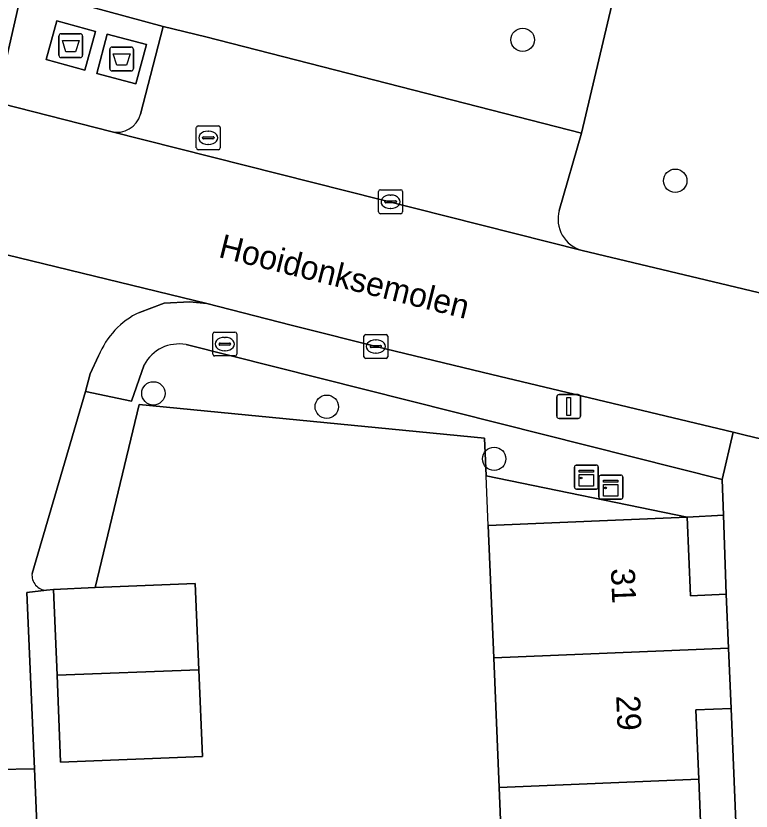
# Model space of a CAD drawing. Extents: x 161241 to 161758, y 384138 to 384885.
# Drawn here: x 161336.04 to 161366.81, y 384281.92 to 384315.21 of the extents above; entities that cross this region are included whole.
import ezdxf

# ---------------------------------------------------------------- set-up
doc = ezdxf.new("R2010")
doc.units = 0
for name, color, linetype in [('IMGEO_Afval_apart_plaats', 7, 'Continuous'), ('IMGEO_Boom', 7, 'Continuous'), ('IMGEO_Erf', 7, 'Continuous'), ('IMGEO_Groenvoorziening', 7, 'Continuous'), ('IMGEO_Hek', 7, 'Continuous'), ('IMGEO_Kast', 7, 'Continuous'), ('IMGEO_Kolk', 7, 'Continuous'), ('IMGEO_Lichtmast', 7, 'Continuous'), ('IMGEO_Openbare_ruimte_label', 7, 'Continuous'), ('IMGEO_Pand', 7, 'Continuous'), ('IMGEO_Pand_nummerreeks', 7, 'Continuous'), ('IMGEO_Parkeervlak_open', 7, 'Continuous'), ('IMGEO_Rijbaan_lokaal_open', 7, 'Continuous'), ('IMGEO_Rioolput', 7, 'Continuous'), ('IMGEO_Voetpad_gesloten', 7, 'Continuous'), ('IMGEO_Voetpad_open', 7, 'Continuous')]:
    doc.layers.add(name, color=color, linetype=linetype)

msp = doc.modelspace()

# ---------------------------------------------------------------- linework, layer by layer
at = {"layer": 'IMGEO_Afval_apart_plaats'}
for p, q in [((161337.939, 384314.467), (161338.729, 384314.467)), ((161338.729, 384314.467), (161337.939, 384314.467)), ((161337.839, 384313.567), (161337.839, 384314.367)), ((161337.839, 384314.367), (161337.839, 384313.567)), ((161338.829, 384314.367), (161338.829, 384313.567)), ((161338.829, 384313.567), (161338.829, 384314.367)), ((161339.968, 384313.008), (161339.968, 384313.808)), ((161339.968, 384313.808), (161339.968, 384313.008)), ((161340.068, 384313.908), (161340.858, 384313.908)), ((161340.858, 384313.908), (161340.068, 384313.908)), ((161340.958, 384313.808), (161340.958, 384313.008)), ((161340.958, 384313.008), (161340.958, 384313.808)), ((161338.729, 384313.467), (161337.939, 384313.467)), ((161337.939, 384313.467), (161338.729, 384313.467)), ((161340.858, 384312.908), (161340.068, 384312.908)), ((161340.068, 384312.908), (161340.858, 384312.908))]:
    msp.add_line(p, q, dxfattribs=at)
for points in [[(161337.982, 384314.181), (161338.686, 384314.181), (161338.537, 384313.711), (161338.131, 384313.711), (161337.982, 384314.181)], [(161340.111, 384313.622), (161340.815, 384313.622), (161340.666, 384313.152), (161340.26, 384313.152), (161340.111, 384313.622)]]:
    msp.add_lwpolyline(points, dxfattribs=at)
for centre, start, end in [((161337.939, 384314.367), 90, 180), ((161337.939, 384314.367), 90, 180), ((161338.729, 384314.367), 0, 90), ((161338.729, 384314.367), 360, 90), ((161340.068, 384313.808), 90, 180), ((161340.068, 384313.808), 90, 180), ((161340.858, 384313.808), 0, 90), ((161340.858, 384313.808), 360, 90), ((161337.939, 384313.567), 180, 270), ((161337.939, 384313.567), 180, 270), ((161338.729, 384313.567), 270, 0), ((161338.729, 384313.567), 270, 0), ((161340.068, 384313.008), 180, 270), ((161340.068, 384313.008), 180, 270), ((161340.858, 384313.008), 270, 0), ((161340.858, 384313.008), 270, 0)]:
    msp.add_arc(centre, 0.1, start, end, dxfattribs=at)
at = {"layer": 'IMGEO_Boom'}
for centre in [(161357.246, 384314.213), (161363.632, 384308.312), (161341.792, 384299.412), (161349.048, 384298.852), (161356.052, 384296.67)]:
    msp.add_circle(centre, 0.489, dxfattribs=at)
at = {"layer": 'IMGEO_Erf'}
msp.add_lwpolyline([(161356.488, 384277.486), (161356.262, 384282.909), (161356.035, 384288.333), (161355.803, 384293.876), (161364.129, 384294.223), (161355.716, 384295.962), (161355.65, 384297.533), (161341.191, 384298.94), (161339.356, 384291.278), (161343.541, 384291.452), (161343.692, 384287.843), (161343.843, 384284.212), (161337.91, 384283.965), (161337.758, 384287.607), (161337.608, 384291.205), (161337.32, 384291.17), (161336.501, 384291.074), (161336.819, 384283.698), (161338.239, 384250)], dxfattribs=at)
for points in [[(161364.129, 384294.223), (161364.266, 384290.938), (161365.768, 384291), (161365.649, 384294.31)], [(161365.967, 384286.221), (161364.492, 384286.16), (161364.613, 384283.257), (161364.747, 384280.045), (161366.223, 384280.106)]]:
    msp.add_lwpolyline(points, close=True, dxfattribs=at)
at = {"layer": 'IMGEO_Groenvoorziening'}
for points in [[(161359.736, 384305.395), (161365.529, 384304.017), (161372.24, 384302.407), (161373.142, 384302.222), (161374.439, 384312.732), (161374.623, 384314.221), (161375.299, 384319.702), (161358.812, 384321.618), (161359.31, 384326.016), (161359.827, 384330.585), (161358.63, 384330.717), (161361.21, 384352.499), (161349.287, 384353.883), (161348.839, 384353.935), (161345.806, 384318.051), (161360.974, 384315.683), (161359.706, 384310.307), (161358.781, 384307.069)], [(161328.866, 384324.519), (161328.421, 384321.506), (161295.885, 384325.211), (161295.467, 384325.102), (161295.374, 384323.02), (161335.524, 384312.89), (161338.358, 384325.391), (161331.006, 384326.163)], [(161337.32, 384291.17), (161337.608, 384291.205), (161339.356, 384291.278), (161341.191, 384298.94), (161355.65, 384297.533), (161355.716, 384295.962), (161364.129, 384294.223), (161365.649, 384294.31), (161365.595, 384295.806), (161343.158, 384301.452)], [(161341.404, 384300.609), (161340.871, 384299.087), (161338.948, 384299.496), (161336.713, 384291.871)]]:
    msp.add_lwpolyline(points, dxfattribs=at)
msp.add_lwpolyline([(161337.862, 384317.338), (161337.568, 384316.046), (161342.197, 384314.772), (161343.987, 384314.34), (161359.706, 384310.307), (161360.974, 384315.683), (161345.806, 384318.051), (161338.281, 384319.226)], close=True, dxfattribs=at)
for centre, radius, start, end in [((161360.076, 384306.698), 1.347, 164.0327, 255.3759), ((161342.862, 384299.822), 1.657, 79.7112, 151.6282), ((161337.341, 384291.801), 0.631, 173.6444, 268.1346)]:
    msp.add_arc(centre, radius, start, end, dxfattribs=at)
at = {"layer": 'IMGEO_Hek'}
msp.add_lwpolyline([(161355.803, 384293.876), (161355.716, 384295.962)], dxfattribs=at)
at = {"layer": 'IMGEO_Kast'}
for p, q in [((161359.411, 384295.48), (161359.411, 384296.321)), ((161359.411, 384296.321), (161359.411, 384295.48)), ((161359.486, 384296.405), (161360.327, 384296.405)), ((161360.327, 384296.405), (161359.486, 384296.405)), ((161360.411, 384296.33), (161360.411, 384295.489)), ((161360.411, 384295.489), (161360.411, 384296.33)), ((161360.439, 384295.062), (161360.439, 384295.903)), ((161360.439, 384295.903), (161360.439, 384295.062)), ((161360.514, 384295.987), (161361.355, 384295.987)), ((161361.355, 384295.987), (161360.514, 384295.987)), ((161361.439, 384295.912), (161361.439, 384295.071)), ((161361.439, 384295.071), (161361.439, 384295.912)), ((161360.336, 384295.405), (161359.495, 384295.405)), ((161359.495, 384295.405), (161360.336, 384295.405)), ((161361.364, 384294.987), (161360.523, 384294.987)), ((161360.523, 384294.987), (161361.364, 384294.987))]:
    msp.add_line(p, q, dxfattribs=at)
for points in [[(161359.606, 384296.195), (161360.206, 384296.195), (161360.206, 384296.11), (161359.606, 384296.11), (161359.606, 384296.195)], [(161359.606, 384296.02), (161360.206, 384296.02), (161360.206, 384295.531), (161359.606, 384295.531), (161359.606, 384296.02)], [(161360.634, 384295.777), (161361.234, 384295.777), (161361.234, 384295.692), (161360.634, 384295.692), (161360.634, 384295.777)], [(161360.634, 384295.602), (161361.234, 384295.602), (161361.234, 384295.113), (161360.634, 384295.113), (161360.634, 384295.602)]]:
    msp.add_lwpolyline(points, dxfattribs=at)
for centre in [(161359.69, 384295.869), (161360.718, 384295.451)]:
    msp.add_circle(centre, 0.0377, dxfattribs=at)
for centre, start, end in [((161359.489, 384296.327), 92.4484, 184.2845), ((161359.489, 384296.327), 92.4484, 184.2845), ((161360.333, 384296.327), 2.4484, 94.2845), ((161360.333, 384296.327), 2.4484, 94.2845), ((161360.517, 384295.909), 92.4484, 184.2845), ((161360.517, 384295.909), 92.4484, 184.2845), ((161361.361, 384295.909), 2.4484, 94.2845), ((161361.361, 384295.909), 2.4484, 94.2845), ((161359.489, 384295.483), 182.4484, 274.2845), ((161359.489, 384295.483), 182.4484, 274.2845), ((161360.333, 384295.483), 272.4484, 4.2845), ((161360.333, 384295.483), 272.4484, 4.2845), ((161360.517, 384295.065), 182.4484, 274.2845), ((161360.517, 384295.065), 182.4484, 274.2845), ((161361.361, 384295.065), 272.4484, 4.2845), ((161361.361, 384295.065), 272.4484, 4.2845)]:
    msp.add_arc(centre, 0.0779, start, end, dxfattribs=at)
at = {"layer": 'IMGEO_Kolk'}
for p, q in [((161351.219, 384307.008), (161351.219, 384307.86)), ((161351.294, 384307.934), (161352.146, 384307.934)), ((161352.22, 384307.86), (161352.22, 384307.008)), ((161351.478, 384307.428), (161351.478, 384307.44)), ((161351.521, 384307.477), (161351.919, 384307.477)), ((161351.707, 384307.714), (161351.732, 384307.714)), ((161351.962, 384307.44), (161351.962, 384307.428)), ((161351.916, 384307.391), (161351.518, 384307.391)), ((161351.73, 384307.154), (161351.705, 384307.154)), ((161352.146, 384306.934), (161351.294, 384306.934)), ((161350.602, 384300.947), (161350.602, 384301.799)), ((161350.677, 384301.873), (161351.529, 384301.873)), ((161351.603, 384301.799), (161351.603, 384300.947)), ((161350.904, 384301.416), (161351.302, 384301.416)), ((161351.09, 384301.653), (161351.115, 384301.653)), ((161350.861, 384301.367), (161350.861, 384301.379)), ((161351.299, 384301.33), (161350.901, 384301.33)), ((161351.113, 384301.093), (161351.088, 384301.093)), ((161351.345, 384301.379), (161351.345, 384301.367)), ((161351.529, 384300.873), (161350.677, 384300.873))]:
    msp.add_line(p, q, dxfattribs=at)
for points in [[(161351.219, 384307.008), (161351.219, 384307.86)], [(161351.294, 384307.934), (161352.146, 384307.934)], [(161352.22, 384307.86), (161352.22, 384307.008)], [(161352.146, 384306.934), (161351.294, 384306.934)], [(161350.602, 384300.947), (161350.602, 384301.799)], [(161350.677, 384301.873), (161351.529, 384301.873)], [(161351.603, 384301.799), (161351.603, 384300.947)], [(161351.529, 384300.873), (161350.677, 384300.873)]]:
    msp.add_lwpolyline(points, dxfattribs=at)
for centre, radius, start, end in [((161351.296, 384307.858), 0.0765, 91.552, 178.448), ((161351.296, 384307.858), 0.0765, 91.552, 178.448), ((161352.144, 384307.858), 0.0765, 1.552, 88.448), ((161352.144, 384307.858), 0.0765, 1.552, 88.448), ((161351.518, 384307.437), 0.0403, 85.8775, 175.7526), ((161351.515, 384307.427), 0.0366, 178.938, 274.7102), ((161351.919, 384307.434), 0.043, 264.8664, 352.4533), ((161351.923, 384307.439), 0.0386, 1.7309, 96.639), ((161351.296, 384307.01), 0.0765, 181.552, 268.448), ((161351.296, 384307.01), 0.0765, 181.552, 268.448), ((161352.144, 384307.01), 0.0765, 271.552, 358.448), ((161352.144, 384307.01), 0.0765, 271.552, 358.448), ((161350.679, 384301.797), 0.0765, 91.552, 178.448), ((161350.679, 384301.797), 0.0765, 91.552, 178.448), ((161351.527, 384301.797), 0.0765, 1.552, 88.448), ((161351.527, 384301.797), 0.0765, 1.552, 88.448), ((161350.901, 384301.376), 0.0403, 85.8775, 175.7526), ((161351.306, 384301.378), 0.0386, 1.7309, 96.639), ((161350.898, 384301.366), 0.0366, 178.938, 274.7102), ((161351.302, 384301.373), 0.043, 264.8664, 352.4533), ((161350.679, 384300.949), 0.0765, 181.552, 268.448), ((161350.679, 384300.949), 0.0765, 181.552, 268.448), ((161351.527, 384300.949), 0.0765, 271.552, 358.448), ((161351.527, 384300.949), 0.0765, 271.552, 358.448)]:
    msp.add_arc(centre, radius, start, end, dxfattribs=at)
for centre, major_axis, ratio, start_param, end_param in [((161351.706, 384307.434), (-0.387, 0.002), 0.722429, 4.712389, 7.853982), ((161351.731, 384307.434), (-0.39, 0.002), 0.717154, 1.570796, 4.712389), ((161351.089, 384301.373), (-0.387, 0.002), 0.722429, 4.712389, 7.853982), ((161351.114, 384301.373), (-0.39, 0.002), 0.717154, 1.570796, 4.712389)]:
    msp.add_ellipse(centre, major_axis=major_axis, ratio=ratio, start_param=start_param, end_param=end_param, dxfattribs=at)
at = {"layer": 'IMGEO_Lichtmast'}
for p, q in [((161358.674, 384298.46), (161358.674, 384299.26)), ((161358.674, 384299.26), (161358.674, 384298.46)), ((161358.774, 384299.36), (161359.564, 384299.36)), ((161359.564, 384299.36), (161358.774, 384299.36)), ((161359.664, 384299.26), (161359.664, 384298.46)), ((161359.664, 384298.46), (161359.664, 384299.26)), ((161359.564, 384298.36), (161358.774, 384298.36)), ((161358.774, 384298.36), (161359.564, 384298.36))]:
    msp.add_line(p, q, dxfattribs=at)
msp.add_lwpolyline([(161359.094, 384299.235), (161359.244, 384299.235), (161359.244, 384298.485), (161359.094, 384298.485), (161359.094, 384299.235)], dxfattribs=at)
for centre, start, end in [((161358.774, 384299.26), 90, 180), ((161358.774, 384299.26), 90, 180), ((161359.564, 384299.26), 0, 90), ((161359.564, 384299.26), 360, 90), ((161358.774, 384298.46), 180, 270), ((161358.774, 384298.46), 180, 270), ((161359.564, 384298.46), 270, 0), ((161359.564, 384298.46), 270, 0)]:
    msp.add_arc(centre, 0.1, start, end, dxfattribs=at)
at = {"layer": 'IMGEO_Pand'}
for points in [[(161365.768, 384291), (161364.266, 384290.938), (161364.129, 384294.223), (161355.803, 384293.876), (161356.035, 384288.333), (161365.862, 384288.743)], [(161337.608, 384291.205), (161337.758, 384287.607), (161343.692, 384287.843), (161343.541, 384291.452), (161339.356, 384291.278)], [(161365.862, 384288.743), (161356.035, 384288.333), (161356.262, 384282.909), (161364.613, 384283.257), (161364.492, 384286.16), (161365.967, 384286.221)], [(161337.758, 384287.607), (161337.91, 384283.965), (161343.843, 384284.212), (161343.692, 384287.843)], [(161366.223, 384280.106), (161364.747, 384280.045), (161364.613, 384283.257), (161356.262, 384282.909), (161356.488, 384277.486), (161366.315, 384277.896)]]:
    msp.add_lwpolyline(points, close=True, dxfattribs=at)
at = {"layer": 'IMGEO_Parkeervlak_open'}
for points in [[(161358.781, 384307.069), (161359.706, 384310.307), (161343.987, 384314.34), (161342.197, 384314.772), (161341.253, 384311.101)], [(161340.013, 384310.37), (161359.736, 384305.395)]]:
    msp.add_lwpolyline(points, dxfattribs=at)
for centre, radius, start, end in [((161340.26, 384311.368), 1.028, 256.0742, 344.9659), ((161360.076, 384306.698), 1.347, 164.0327, 255.3759)]:
    msp.add_arc(centre, radius, start, end, dxfattribs=at)
at = {"layer": 'IMGEO_Rijbaan_lokaal_open'}
for points in [[(161314.233, 384310.619), (161318.239, 384309.618), (161324.227, 384308.123), (161331.236, 384306.334), (161332.498, 384305.981), (161344.034, 384303.169), (161347.56, 384302.264), (161351.506, 384301.273), (161355.95, 384300.205), (161366.059, 384297.781), (161366.499, 384297.676), (161371.443, 384296.485), (161372.24, 384302.407), (161365.529, 384304.017), (161359.736, 384305.395), (161340.013, 384310.37), (161334.145, 384311.868), (161312.768, 384317.162), (161299.409, 384320.514), (161296.499, 384321.254), (161295.059, 384315.515), (161302.851, 384313.529), (161304.825, 384312.536)], [(161341.207, 384302.802), (161342.239, 384303.19), (161343.315, 384303.25), (161344.034, 384303.169), (161332.498, 384305.981)], [(161334.475, 384301.885), (161334.078, 384300.633), (161331.745, 384292.799), (161333.39, 384292.341), (161333.505, 384290.009), (161333.601, 384287.108), (161333.712, 384285.206), (161333.749, 384283.665), (161335.259, 384283.661), (161336.819, 384283.698), (161336.501, 384291.074), (161337.32, 384291.17)], [(161338.948, 384299.496), (161339.149, 384300.233), (161339.5, 384300.988)], [(161336.713, 384291.871), (161338.948, 384299.496)]]:
    msp.add_lwpolyline(points, dxfattribs=at)
for centre, radius, start, end in [((161342.692, 384299.695), 3.444, 115.5396, 157.9416), ((161337.341, 384291.801), 0.631, 173.6444, 268.1346)]:
    msp.add_arc(centre, radius, start, end, dxfattribs=at)
at = {"layer": 'IMGEO_Rioolput'}
for p, q in [((161343.589, 384309.684), (161343.589, 384310.536)), ((161343.664, 384310.61), (161344.516, 384310.61)), ((161344.59, 384310.536), (161344.59, 384309.684)), ((161343.848, 384310.104), (161343.848, 384310.116)), ((161343.891, 384310.153), (161344.289, 384310.153)), ((161344.077, 384310.39), (161344.102, 384310.39)), ((161344.332, 384310.116), (161344.332, 384310.104)), ((161344.286, 384310.067), (161343.888, 384310.067)), ((161344.1, 384309.83), (161344.075, 384309.83)), ((161344.516, 384309.61), (161343.664, 384309.61)), ((161344.28, 384301.05), (161344.28, 384301.902)), ((161344.355, 384301.976), (161345.207, 384301.976)), ((161344.768, 384301.756), (161344.793, 384301.756)), ((161345.281, 384301.902), (161345.281, 384301.05)), ((161344.539, 384301.47), (161344.539, 384301.482)), ((161344.977, 384301.433), (161344.579, 384301.433)), ((161344.582, 384301.519), (161344.98, 384301.519)), ((161345.023, 384301.482), (161345.023, 384301.47)), ((161344.791, 384301.196), (161344.766, 384301.196)), ((161345.207, 384300.976), (161344.355, 384300.976))]:
    msp.add_line(p, q, dxfattribs=at)
for points in [[(161343.589, 384309.684), (161343.589, 384310.536)], [(161343.664, 384310.61), (161344.516, 384310.61)], [(161344.59, 384310.536), (161344.59, 384309.684)], [(161344.516, 384309.61), (161343.664, 384309.61)], [(161344.28, 384301.05), (161344.28, 384301.902)], [(161344.355, 384301.976), (161345.207, 384301.976)], [(161345.281, 384301.902), (161345.281, 384301.05)], [(161345.207, 384300.976), (161344.355, 384300.976)]]:
    msp.add_lwpolyline(points, dxfattribs=at)
for centre, radius, start, end in [((161343.666, 384310.534), 0.0765, 91.552, 178.448), ((161343.666, 384310.534), 0.0765, 91.552, 178.448), ((161344.514, 384310.534), 0.0765, 1.552, 88.448), ((161344.514, 384310.534), 0.0765, 1.552, 88.448), ((161343.888, 384310.113), 0.0403, 85.8775, 175.7526), ((161343.885, 384310.103), 0.0366, 178.938, 274.7102), ((161344.289, 384310.11), 0.043, 264.8664, 352.4533), ((161344.293, 384310.115), 0.0386, 1.7309, 96.639), ((161343.666, 384309.686), 0.0765, 181.552, 268.448), ((161343.666, 384309.686), 0.0765, 181.552, 268.448), ((161344.514, 384309.686), 0.0765, 271.552, 358.448), ((161344.514, 384309.686), 0.0765, 271.552, 358.448), ((161344.357, 384301.9), 0.0765, 91.552, 178.448), ((161344.357, 384301.9), 0.0765, 91.552, 178.448), ((161345.205, 384301.9), 0.0765, 1.552, 88.448), ((161345.205, 384301.9), 0.0765, 1.552, 88.448), ((161344.579, 384301.479), 0.0403, 85.8775, 175.7526), ((161344.576, 384301.469), 0.0366, 178.938, 274.7102), ((161344.98, 384301.476), 0.043, 264.8664, 352.4533), ((161344.984, 384301.481), 0.0386, 1.7309, 96.639), ((161344.357, 384301.052), 0.0765, 181.552, 268.448), ((161344.357, 384301.052), 0.0765, 181.552, 268.448), ((161345.205, 384301.052), 0.0765, 271.552, 358.448), ((161345.205, 384301.052), 0.0765, 271.552, 358.448)]:
    msp.add_arc(centre, radius, start, end, dxfattribs=at)
for centre, major_axis, ratio, start_param, end_param in [((161344.076, 384310.11), (-0.387, 0.002), 0.722429, 4.712389, 7.853982), ((161344.101, 384310.11), (-0.39, 0.002), 0.717154, 1.570796, 4.712389), ((161344.767, 384301.476), (-0.387, 0.002), 0.722429, 4.712389, 7.853982), ((161344.792, 384301.476), (-0.39, 0.002), 0.717154, 1.570796, 4.712389)]:
    msp.add_ellipse(centre, major_axis=major_axis, ratio=ratio, start_param=start_param, end_param=end_param, dxfattribs=at)
at = {"layer": 'IMGEO_Voetpad_gesloten'}
for points in [[(161339.366, 384314.556), (161337.747, 384315.001), (161337.302, 384313.383), (161338.921, 384312.938)], [(161341.5, 384314.016), (161339.863, 384314.452), (161339.423, 384312.8), (161341.06, 384312.364)]]:
    msp.add_lwpolyline(points, close=True, dxfattribs=at)
at = {"layer": 'IMGEO_Voetpad_open'}
for points in [[(161378.13, 384345.016), (161376.699, 384333.039), (161376.372, 384330.142), (161375.754, 384324.126), (161375.299, 384319.702), (161374.623, 384314.221), (161374.439, 384312.732), (161373.142, 384302.222), (161372.24, 384302.407), (161371.443, 384296.485), (161366.499, 384297.676), (161366.059, 384297.781), (161365.595, 384295.806), (161365.649, 384294.31), (161365.768, 384291), (161365.862, 384288.743), (161365.967, 384286.221), (161366.223, 384280.106)], [(161341.253, 384311.101), (161342.197, 384314.772), (161337.568, 384316.046), (161337.862, 384317.338), (161338.281, 384319.226), (161339.593, 384325.267), (161339.428, 384325.279), (161338.358, 384325.391), (161335.524, 384312.89), (161295.374, 384323.02), (161295.467, 384325.102), (161295.885, 384325.211), (161296.198, 384328.486)], [(161293.892, 384321.916), (161296.499, 384321.254), (161299.409, 384320.514), (161312.768, 384317.162), (161334.145, 384311.868), (161340.013, 384310.37)], [(161355.95, 384300.205), (161351.506, 384301.273), (161347.56, 384302.264), (161344.034, 384303.169), (161343.315, 384303.25), (161342.239, 384303.19), (161341.207, 384302.802)], [(161343.158, 384301.452), (161365.595, 384295.806), (161366.059, 384297.781), (161355.95, 384300.205)], [(161339.5, 384300.988), (161339.149, 384300.233), (161338.948, 384299.496), (161340.871, 384299.087), (161341.404, 384300.609)], [(161340.006, 384208.085), (161338.239, 384250), (161336.819, 384283.698), (161335.259, 384283.661), (161333.749, 384283.665), (161333.712, 384285.206), (161333.601, 384287.108), (161333.505, 384290.009), (161333.39, 384292.341), (161331.745, 384292.799), (161329.259, 384284.454), (161329.521, 384278.565), (161329.796, 384278.607), (161331.584, 384278.687), (161333.256, 384278.821), (161334.887, 384278.846), (161335.107, 384273.512), (161335.328, 384268.908), (161335.543, 384263.223), (161335.741, 384258.44), (161336.134, 384250), (161336.225, 384248.01), (161336.684, 384236.002)]]:
    msp.add_lwpolyline(points, dxfattribs=at)
for points in [[(161337.747, 384315.001), (161339.366, 384314.556), (161338.921, 384312.938), (161337.302, 384313.383)], [(161339.863, 384314.452), (161341.5, 384314.016), (161341.06, 384312.364), (161339.423, 384312.8)]]:
    msp.add_lwpolyline(points, close=True, dxfattribs=at)
for centre, radius, start, end in [((161340.26, 384311.368), 1.028, 256.0742, 344.9659), ((161342.692, 384299.695), 3.444, 115.5396, 157.9416), ((161342.862, 384299.822), 1.657, 79.7112, 151.6282)]:
    msp.add_arc(centre, radius, start, end, dxfattribs=at)

# ---------------------------------------------------------------- texts
at = {"layer": 'IMGEO_Openbare_ruimte_label'}
msp.add_text('Hooidonksemolen', height=1, rotation=345.936, dxfattribs=at).set_placement((161344.479, 384305.124))
at = {"layer": 'IMGEO_Pand_nummerreeks'}
for s, p in [('31', (161360.937, 384292.079)), ('29', (161361.16, 384286.754))]:
    msp.add_text(s, height=1, rotation=272.4061, dxfattribs=at).set_placement(p)

doc.saveas('drawing.dxf')
